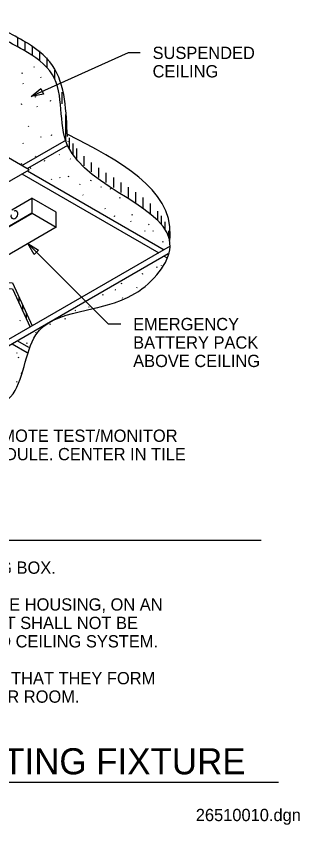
# Model space of a CAD drawing. Extents: x -12191 to -12144.8, y -12274.7 to -12230.3.
# Drawn here: x -12160.21 to -12144.82, y -12274.67 to -12230.78 of the extents above; entities that cross this region are included whole.
import ezdxf

# ---------------------------------------------------------------- set-up
doc = ezdxf.new("R2010")
doc.units = 0
for name, color, linetype in [('G-ANNO-TEXT', 7, 'Continuous'), ('G-DETL-LINE', 7, 'Continuous'), ('G-DETL-OTLN', 7, 'Continuous'), ('G-DETL-PATT', 7, 'Continuous')]:
    doc.layers.add(name, color=color, linetype=linetype)

msp = doc.modelspace()

# ---------------------------------------------------------------- linework, layer by layer
at = {"layer": 'G-ANNO-TEXT'}
for p, q in [((-12154.140250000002, -12232.771531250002), (-12159.400718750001, -12235.136395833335)), ((-12153.473583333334, -12232.771531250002), (-12154.140250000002, -12232.771531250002)), ((-12155.194312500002, -12247.492593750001), (-12159.582510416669, -12243.123781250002)), ((-12154.527645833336, -12247.492593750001), (-12155.194312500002, -12247.492593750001)), ((-12189.480322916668, -12259.228208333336), (-12146.916812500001, -12259.228208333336)), ((-12189.060427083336, -12272.366718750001), (-12145.967760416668, -12272.366718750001))]:
    msp.add_line(p, q, dxfattribs=at)
for points in [[(-12158.724333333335, -12235.015052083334), (-12159.400718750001, -12235.136395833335), (-12158.861010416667, -12234.71103125)], [(-12158.724333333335, -12235.015052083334), (-12159.400718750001, -12235.136395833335), (-12158.861010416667, -12234.71103125)], [(-12159.227656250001, -12243.712250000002), (-12159.582510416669, -12243.123781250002), (-12158.992468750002, -12243.476031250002)], [(-12159.227656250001, -12243.712250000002), (-12159.582510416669, -12243.123781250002), (-12158.992468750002, -12243.476031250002)]]:
    msp.add_lwpolyline(points, close=True, dxfattribs=at)
at = {"layer": 'G-DETL-LINE'}
for p, q in [((-12159.895875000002, -12239.344177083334), (-12152.475625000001, -12243.628260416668)), ((-12159.595875, -12239.170968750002), (-12152.175604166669, -12243.455052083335)), ((-12151.850208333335, -12243.267197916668), (-12175.127875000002, -12256.706531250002)), ((-12151.955645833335, -12243.674468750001), (-12174.56566666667, -12256.728385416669)), ((-12152.175604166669, -12243.801468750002), (-12152.048083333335, -12243.87509375)), ((-12160.430041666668, -12248.567177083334), (-12159.604333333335, -12249.04390625)), ((-12160.130062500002, -12248.393968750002), (-12159.532645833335, -12248.738885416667))]:
    msp.add_line(p, q, dxfattribs=at)
for points in [[(-12159.895875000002, -12238.882302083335), (-12157.475000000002, -12237.484614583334)], [(-12157.416791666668, -12237.797427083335), (-12159.595854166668, -12239.055510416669)], [(-12163.199500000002, -12241.251531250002), (-12162.591104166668, -12245.477947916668), (-12160.408416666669, -12245.581760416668), (-12159.450375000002, -12247.655135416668)], [(-12163.156708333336, -12241.226822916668), (-12162.591104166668, -12245.155927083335), (-12160.408416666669, -12245.259739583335), (-12159.332916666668, -12247.587322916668)]]:
    msp.add_lwpolyline(points, dxfattribs=at)
for points in [[(-12162.524979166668, -12231.370156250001), (-12165.604291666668, -12230.827697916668), (-12169.197666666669, -12232.024093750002), (-12170.826062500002, -12233.033635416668), (-12172.975291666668, -12235.306572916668), (-12175.892979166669, -12236.625718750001), (-12177.556291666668, -12238.679343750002), (-12179.732041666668, -12239.355989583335), (-12182.680437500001, -12241.104593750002), (-12184.707458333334, -12244.110989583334), (-12184.707458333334, -12245.061968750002), (-12183.202541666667, -12252.516572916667), (-12182.588291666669, -12253.252843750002), (-12179.702708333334, -12256.194239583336), (-12174.788729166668, -12256.715760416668), (-12173.683062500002, -12256.715760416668), (-12171.379625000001, -12255.642031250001), (-12168.062687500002, -12253.371906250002), (-12164.407895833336, -12252.328885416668), (-12160.507416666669, -12251.439260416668), (-12159.139520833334, -12248.077489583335), (-12153.765604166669, -12245.839364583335), (-12151.852854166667, -12243.291947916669), (-12157.416791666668, -12237.797427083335), (-12158.232916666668, -12233.959531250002), (-12159.829958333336, -12232.609718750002), (-12162.156541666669, -12231.503885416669), (-12162.497541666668, -12231.378572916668)], [(-12157.416437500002, -12237.303510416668), (-12157.416791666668, -12237.298822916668), (-12158.232916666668, -12233.460947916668), (-12159.829958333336, -12232.111135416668), (-12162.156541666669, -12231.005281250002), (-12162.497541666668, -12230.879968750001)], [(-12151.868520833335, -12242.956218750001), (-12151.852854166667, -12242.684656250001), (-12157.412937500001, -12237.198322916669)]]:
    msp.add_spline(points, degree=3, dxfattribs=at)
at = {"layer": 'G-DETL-OTLN'}
for points in [[(-12184.722729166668, -12244.188677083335), (-12176.504750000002, -12248.933302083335), (-12159.495875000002, -12239.113239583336), (-12167.816104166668, -12234.309552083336), (-12184.694312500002, -12244.054177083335)], [(-12160.434291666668, -12241.292072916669), (-12159.349562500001, -12240.665802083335), (-12159.349562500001, -12241.472697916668), (-12162.443729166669, -12243.259114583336), (-12162.443729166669, -12242.452218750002), (-12160.661291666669, -12241.423135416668)]]:
    msp.add_lwpolyline(points, dxfattribs=at)
for points in [[(-12158.034708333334, -12242.230156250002), (-12158.034708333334, -12241.424947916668), (-12159.349562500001, -12240.665802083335), (-12159.349562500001, -12241.471031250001)], [(-12162.443729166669, -12243.259114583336), (-12159.34810416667, -12241.471864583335), (-12158.034708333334, -12242.230156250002), (-12161.130312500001, -12244.017406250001)]]:
    msp.add_lwpolyline(points, close=True, dxfattribs=at)
msp.add_ellipse((-12160.303916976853, -12241.562953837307), major_axis=(0.11335681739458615, 0.19633976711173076), ratio=0.763774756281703, start_param=2.0063410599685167, end_param=7.128247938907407, dxfattribs=at)
at = {"layer": 'G-DETL-PATT'}
for p, q in [((-12160.118083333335, -12232.458031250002), (-12160.118083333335, -12231.959427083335)), ((-12159.718083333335, -12232.669322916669), (-12159.718083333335, -12232.170572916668)), ((-12159.318083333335, -12232.897010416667), (-12159.318083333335, -12232.395510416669)), ((-12158.918083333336, -12233.171760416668), (-12158.918083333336, -12232.664927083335)), ((-12158.518083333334, -12233.548781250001), (-12158.518083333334, -12233.037218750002)), ((-12159.878250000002, -12233.894302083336), (-12159.856666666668, -12233.845697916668)), ((-12159.252687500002, -12233.506697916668), (-12159.231125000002, -12233.539072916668)), ((-12158.118083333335, -12234.183031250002), (-12158.118083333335, -12233.701781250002)), ((-12158.890812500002, -12234.081385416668), (-12158.869250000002, -12234.113760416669)), ((-12159.844916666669, -12234.42196875), (-12159.823312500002, -12234.454364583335)), ((-12159.160916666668, -12235.167385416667), (-12159.139354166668, -12235.118864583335)), ((-12157.718083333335, -12235.544885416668), (-12157.718083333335, -12234.904822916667)), ((-12157.718083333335, -12235.458885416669), (-12157.718083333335, -12234.904822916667)), ((-12159.928125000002, -12235.524093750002), (-12159.922729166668, -12235.572656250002)), ((-12158.340937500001, -12235.388593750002), (-12158.319354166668, -12235.340072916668)), ((-12159.082395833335, -12235.667197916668), (-12159.060833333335, -12235.699552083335)), ((-12157.518083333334, -12237.521052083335), (-12157.518083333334, -12236.125364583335)), ((-12159.559916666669, -12236.72971875), (-12159.5383125, -12236.762135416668)), ((-12158.890812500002, -12237.316760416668), (-12158.869250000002, -12237.349114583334)), ((-12158.287020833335, -12237.253718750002), (-12158.265416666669, -12237.205156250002)), ((-12159.844916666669, -12237.657322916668), (-12159.823312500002, -12237.689718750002)), ((-12157.394562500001, -12237.598614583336), (-12157.395062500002, -12237.591281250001)), ((-12157.318083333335, -12237.983156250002), (-12157.318083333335, -12237.383489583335)), ((-12157.118083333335, -12238.273343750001), (-12157.118083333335, -12237.699968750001)), ((-12156.918083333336, -12238.507718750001), (-12156.918083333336, -12237.956843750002)), ((-12159.160916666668, -12238.402760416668), (-12159.139354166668, -12238.354218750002)), ((-12158.6765625, -12238.644781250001), (-12158.655000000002, -12238.596260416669)), ((-12157.874333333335, -12238.282489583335), (-12157.852729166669, -12238.314843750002)), ((-12157.273041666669, -12238.514947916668), (-12157.251437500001, -12238.547343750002)), ((-12156.518083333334, -12238.896281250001), (-12156.518083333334, -12238.372552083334)), ((-12159.928125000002, -12238.759447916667), (-12159.922729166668, -12238.808010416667)), ((-12159.443791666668, -12239.001468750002), (-12159.438375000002, -12239.05003125)), ((-12156.118083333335, -12239.228093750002), (-12156.118083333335, -12238.713572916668)), ((-12155.718083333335, -12239.528947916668), (-12155.718083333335, -12239.012177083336)), ((-12157.856583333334, -12239.522510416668), (-12157.834979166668, -12239.554906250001)), ((-12157.365645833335, -12239.49178125), (-12157.344041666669, -12239.443218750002)), ((-12155.318083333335, -12239.811677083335), (-12155.318083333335, -12239.285635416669)), ((-12154.918083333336, -12240.084281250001), (-12154.918083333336, -12239.545302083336)), ((-12158.290791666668, -12239.648760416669), (-12158.269187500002, -12239.600156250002)), ((-12156.748541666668, -12239.923552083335), (-12156.726937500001, -12239.874947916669)), ((-12156.165, -12239.715385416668), (-12156.143395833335, -12239.666781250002)), ((-12154.518083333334, -12240.352822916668), (-12154.518083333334, -12239.80003125)), ((-12155.6140625, -12240.030447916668), (-12155.592479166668, -12240.062843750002)), ((-12155.089604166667, -12240.165031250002), (-12155.068000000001, -12240.116427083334)), ((-12154.118083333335, -12240.622635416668), (-12154.118083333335, -12240.057947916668)), ((-12153.718083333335, -12240.899489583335), (-12153.718083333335, -12240.327927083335)), ((-12156.5894375, -12240.471760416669), (-12156.567854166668, -12240.504156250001)), ((-12154.581062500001, -12240.656322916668), (-12154.559479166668, -12240.607718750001)), ((-12153.318083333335, -12241.190822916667), (-12153.318083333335, -12240.621406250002)), ((-12155.397333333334, -12241.204531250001), (-12155.375729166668, -12241.236947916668)), ((-12152.918083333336, -12241.508197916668), (-12152.918083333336, -12240.956093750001)), ((-12154.881187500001, -12241.655531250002), (-12154.859583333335, -12241.606947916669)), ((-12153.914166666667, -12241.58059375), (-12153.892562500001, -12241.532010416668)), ((-12152.518083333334, -12241.874281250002), (-12152.518083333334, -12241.366052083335)), ((-12152.318083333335, -12242.091739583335), (-12152.318083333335, -12241.622531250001)), ((-12154.005145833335, -12241.89565625), (-12153.983541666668, -12241.928072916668)), ((-12153.022166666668, -12242.113531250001), (-12153.000562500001, -12242.064927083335)), ((-12152.118083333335, -12242.356156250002), (-12152.118083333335, -12241.945656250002)), ((-12153.246520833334, -12242.420260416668), (-12153.224916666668, -12242.452656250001)), ((-12152.796354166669, -12242.420260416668), (-12152.774750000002, -12242.452656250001)), ((-12151.918083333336, -12242.748843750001), (-12151.918083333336, -12242.425260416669)), ((-12152.2551875, -12243.037822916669), (-12152.233604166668, -12242.98921875)), ((-12152.318083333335, -12244.322656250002), (-12152.318083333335, -12244.310260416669)), ((-12153.332979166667, -12244.798677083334), (-12153.347645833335, -12244.747635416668)), ((-12152.562645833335, -12244.441072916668), (-12152.577291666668, -12244.390010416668)), ((-12154.489333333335, -12245.30938541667), (-12154.467770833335, -12245.260843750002)), ((-12154.848812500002, -12245.618968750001), (-12154.817437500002, -12245.642031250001)), ((-12153.669354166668, -12245.530593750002), (-12153.647750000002, -12245.482072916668)), ((-12160.060645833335, -12246.012385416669), (-12160.060645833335, -12246.310322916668)), ((-12155.497187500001, -12245.922906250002), (-12155.493520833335, -12245.869947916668)), ((-12154.440354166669, -12246.093906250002), (-12154.41875, -12246.045385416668)), ((-12159.860645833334, -12246.445239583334), (-12159.860645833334, -12246.767260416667)), ((-12156.253395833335, -12246.601635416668), (-12156.268041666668, -12246.550572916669)), ((-12159.660645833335, -12246.878072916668), (-12159.660645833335, -12247.200093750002)), ((-12157.032395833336, -12246.737093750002), (-12156.995020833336, -12246.748031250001)), ((-12155.803000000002, -12246.645510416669), (-12155.817666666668, -12246.594468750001)), ((-12159.996437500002, -12247.322906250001), (-12159.974875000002, -12247.274385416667)), ((-12157.537729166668, -12247.244468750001), (-12157.552375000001, -12247.193427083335)), ((-12158.353437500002, -12247.532281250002), (-12158.368104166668, -12247.48126041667)), ((-12159.124416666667, -12247.974385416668), (-12159.139083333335, -12247.923343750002)), ((-12159.617000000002, -12248.566218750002), (-12159.631666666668, -12248.515197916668)), ((-12160.195479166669, -12249.033739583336), (-12160.173875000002, -12249.066135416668)), ((-12160.088729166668, -12249.318802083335), (-12160.067125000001, -12249.270281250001)), ((-12159.917416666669, -12250.174468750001), (-12159.8958125, -12250.125947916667)), ((-12160.181541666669, -12250.652218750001), (-12160.159937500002, -12250.603697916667))]:
    msp.add_line(p, q, dxfattribs=at)

# ---------------------------------------------------------------- texts
at = {"layer": 'G-ANNO-TEXT'}
for s, height, p in [('SUSPENDED', 0.6666666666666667, (-12152.806916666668, -12233.104864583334)), ('CEILING', 0.6666666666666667, (-12152.806916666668, -12234.104864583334)), ('EMERGENCY', 0.6666666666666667, (-12153.860979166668, -12247.825927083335)), ('BATTERY PACK', 0.6666666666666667, (-12153.860979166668, -12248.825927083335)), ('ABOVE CEILING', 0.6666666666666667, (-12153.860979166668, -12249.825927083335)), ('REMOTE TEST/MONITOR', 0.6666666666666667, (-12162.248437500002, -12253.885093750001)), ('MODULE. CENTER IN TILE', 0.6666666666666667, (-12162.248437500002, -12254.885093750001)), ('INSTALL REMOTE TEST/MONITOR MODULE IN A SINGLE GANG BOX.', 0.6666666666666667, (-12187.530458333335, -12261.045843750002)), ('MOUNT EMERGENCY BATTERY PACK ON TOP OF THE FIXTURE HOUSING, ON AN', 0.6666666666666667, (-12187.530458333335, -12263.045843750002)), ('ADJACENT WALL OR ON BUILDING STRUCTURAL MEMBERS. IT SHALL NOT BE', 0.6666666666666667, (-12187.530458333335, -12264.045843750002)), ('MOUNTED TO MECHANICAL EQUIPMENT OR THE SUSPENDED CEILING SYSTEM.', 0.6666666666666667, (-12187.530458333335, -12265.045843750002)), ('LOCATE REMOTE TEST/MONITOR MODULES IDENTICALLY SO THAT THEY FORM', 0.6666666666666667, (-12187.530458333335, -12267.045843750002)), ('A STRAIGHT LINE WHEN VIEWED FROM END OF CORRIDOR OR ROOM.', 0.6666666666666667, (-12187.530458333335, -12268.045843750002)), ('RECESSED EMERGENCY LIGHTING FIXTURE', 1.4166666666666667, (-12189.022488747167, -12271.934260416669)), ('26510010.dgn', 0.6666666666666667, (-12150.462479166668, -12274.473125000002))]:
    msp.add_text(s, height=height, dxfattribs=at).set_placement(p)

doc.saveas('drawing.dxf')
